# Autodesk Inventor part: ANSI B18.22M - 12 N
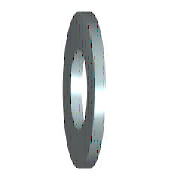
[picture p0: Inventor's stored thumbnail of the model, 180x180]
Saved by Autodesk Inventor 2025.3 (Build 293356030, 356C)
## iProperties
IsCustomPart: 0
Created: 2024-01
Part Number: ANSI B18.22M - 12 N
Material: Acero, suave
Description: Arandelas métricas planas
Document SubType Name: Modeling
Standard: ANSI B18.22M
Designer: User
Standard Revision: 2005
Standards Organization: ANSI
Language: es-ES
Size Designation: 12 N
Categories: <MemberInstance><Categories><Category DisplayName="Fijaciones" InternalName="e4da775c-781d-43d5-af7c-5136215cf5a6" Mnemonic="FSTN"><Category DisplayName="Arande
Density: 7.85 g/cm^3
Appearance: Semipulido
Author: User
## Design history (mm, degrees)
workaxis "Work Axis1"
workplane "Work Plane1"
body "Solid1"
sketch "Boceto"
  geometry: C1 r 12.7 at (0, 0); C2 r 6.65 at (0, 0); 1 further point
  constraints: 2 centre point, 2 coincident
  dimensions: "d0" = 13.3 diameter of C2 (= SD1); "d1" = 25.4 diameter of C1 (= SD2)
extrude "Cuerpo" new body sketch "Boceto" distance "d2" = 2.8 (= SD); taper "d3" = 0 deg
other parameters: "SD1" = 13.3 [user parameter; used in 1 equation term], "SD2" = 25.4 [user parameter; used in 1 equation term], "SD" = 2.8 [user parameter; used in 1 equation term], "d4" = 0, "d5" = 0, "d6" = 0, "d7" = 0, "NND" = 12 [user parameter]
